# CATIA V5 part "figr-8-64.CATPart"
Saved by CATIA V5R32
Part number: Part1
Bounding box of the stored display mesh (mm): x -68.924 to 54.237, y -54.052 to 120.856, z 0 to 40
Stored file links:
  D:\PROJECTS\Project 2022\CATIA V5 6R 2022\Resources\Part Files\c08_catia_v5_6r2022_prt\figr-8-64.CATPart
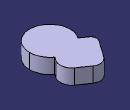
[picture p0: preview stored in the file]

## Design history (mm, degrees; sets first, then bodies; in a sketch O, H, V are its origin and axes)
Body1 (main body)
  Sketch1 on xy-plane, origin (0, 0, 0), H (1, 0, 0), V (0, 1, 0)
    circle A1 centre (0, 0) radius 54.2371
    point P1 (0, 54.2371)
    coincidence: A1 P1, P1 V
  Pad1: profile Sketch1, direction (0, 0, 1), length 40
  Body2
    Sketch2 on xy-plane, origin (0, 0, 0), H (1, 0, 0), V (0, 1, 0)
      line L1 (0, 0) -> (36.9865, 52.8223)
      arc A1 centre (11.6298, 70.5772) radius 30.9549 from (36.9865, 52.8223) to (29.3848, 95.934) ccw
      line L2 (29.3848, 95.934) -> (0.2008, 116.3688)
      arc A2 centre (-14.1853, 95.8234) radius 25.0814 from (0.2008, 116.3688) to (-34.7307, 110.2094) ccw
      line L3 (-34.7307, 110.2094) -> (-66.0893, 65.4248)
      arc A3 centre (-53.2403, 56.4279) radius 15.6856 from (-66.0893, 65.4248) to (-62.2373, 43.579) ccw
      line L4 (-62.2373, 43.579) -> (0, 0)
      tangency: A1 L1, L2 A1, A2 L2, L3 A2, A3 L3, L4 A3
    Pad2: profile Sketch2, direction (0, 0, 1), length 40
  Add1: tool Body2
